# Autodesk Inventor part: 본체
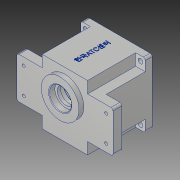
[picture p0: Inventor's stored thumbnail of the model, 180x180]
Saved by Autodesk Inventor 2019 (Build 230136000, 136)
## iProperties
Created: 2020-01
Part Number: 본체
Material: 알루미늄 6061
Document SubType Name: Modeling
Designer: 323-8
Density: 2.7 g/cm^3
Appearance: 알루미늄 - 평지
Mass: 876.342 g
Surface Area: 793.819 cm^2
Volume: 324.571 cm^3
Author: 323-8
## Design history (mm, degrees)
sketch "스케치1"
  geometry: L1 (-47, 47)-(47, 47); L2 (47, 47)-(47, -47); L3 (47, -47)-(-47, -47); L4 (-47, -47)-(-47, 47); L5 (-47, 47)-(47, -47); L6 (47, 47)-(-47, -47); L7 (-70, 30)-(70, 30); L8 (70, 30)-(70, -30); L9 (70, -30)-(-70, -30); L10 (-70, -30)-(-70, 30); L11 (-70, 30)-(70, -30); L12 (70, 30)-(-70, -30); 1 further point
  constraints: 24 end point, 4 midpoint, 4 parallel, 2 horizontal, 2 perpendicular
  dimensions: "d0" = 94 distance of L2.end L3.end; "d1" = 94 distance of L1.end L2.end; "d2" = 140 distance of L8.end L9.end; "d3" = 60 distance of L7.end L8.end
extrude "돌출1" new body sketch "스케치1" distance "d4" = 80; taper "d5" = 0 deg
sketch "스케치2"
  geometry: L1 (-33, 30)-(33, 30); L2 (33, 30)-(33, -30); L3 (33, -30)-(-33, -30); L4 (-33, -30)-(-33, 30); L5 (-33, 30)-(33, -30); L6 (33, 30)-(-33, -30); L7 (47, 47)-(47, 30) reference; L8 (33, 30)-(47, 30); L9 (47, 30)-(47, 47); L10 (47, 47)-(33, 47); L11 (33, 47)-(33, 30); 1 further point
  constraints: 20 end point, 4 parallel, 2 horizontal, 2 midpoint, 2 perpendicular
  dimensions: "d6" = 66 distance of L2.end L3.end; "d7" = 60 distance of L1.end L2.end
extrude "돌출2" cut sketch "스케치2" distance "d8" = 70; taper "d9" = 0 deg
sketch "스케치3"
  geometry: C1 r 27.5 at (0, 11); 1 further point
  constraints: 1 centre point, 1 vertical alignment
  dimensions: "d10" = 55 diameter of C1; "d11" = 11 distance of C1.centre point (0, 0)
extrude "돌출3" join sketch "스케치3" distance "d12" = 7; taper "d13" = 0 deg
sketch "스케치4"
  geometry: C1 r 40 at (0, 0); 1 further point
  constraints: 1 centre point, 1 coincident
  dimensions: "d14" = 80 diameter of C1
extrude "돌출4" cut sketch "스케치4" distance "d15" = 71; taper "d16" = 0 deg
sketch "스케치5"
  geometry: C1 r 43 at (0, 0); 1 further point
  constraints: 1 centre point, 1 coincident
  dimensions: "d17" = 86 diameter of C1
extrude "돌출5" cut sketch "스케치5" distance "d18" = 9; taper "d19" = 0 deg
sketch "스케치6"
  geometry: C1 r 21 at (0, 11); C2 r 15 at (0, -20); 1 further point
  constraints: 2 centre point, 2 vertical alignment
  dimensions: "d24" = 21 radius of C1; "d25" = 15 radius of C2; "d26" = 11 distance of point (0, 0) C1.centre; "d27" = 20 distance of point (0, 0) C2.centre
extrude "돌출6" join sketch "스케치6" distance "d28" = 7; taper "d29" = 0 deg
sketch "스케치7"
  geometry: C1 r 17.5 at (0, 11); A1 r 21 centre (0, 11) between (8.978, -7.984) and (-8.978, -7.984) reference; 1 further point
  constraints: 1 centre point, 1 coincident
  dimensions: "d30" = 35 diameter of C1
extrude "돌출7" cut sketch "스케치7" distance "d31" = 10; taper "d32" = 0 deg
sketch "스케치8"
  geometry: C1 r 11 at (0, -20); A1 r 15 centre (0, -20) between (-8.978, -7.984) and (8.978, -7.984) reference; 1 further point
  constraints: 1 centre point, 1 coincident
  dimensions: "d33" = 22 diameter of C1
extrude "돌출8" cut sketch "스케치8" distance "d34" = 7; taper "d35" = 0 deg
sketch "스케치9"
  geometry: 1 further point
sketch "스케치10"
  geometry: C1 r 11 at (0, 0) reference; C2 r 9.5 at (0, 0); 1 further point
  constraints: 1 centre point, 1 coincident
  dimensions: "d36" = 19 diameter of C2
extrude "돌출9" cut sketch "스케치10" distance "d37" = 3; taper "d38" = 0 deg
sketch "스케치11"
  geometry: C1 r 16 at (0, 0); C2 r 27.5 at (0, 0) reference; 1 further point
  constraints: 1 centre point, 1 concentric
  dimensions: "d39" = 32 diameter of C1
extrude "돌출10" cut sketch "스케치11" distance "d40" = 8.3; taper "d41" = 0 deg
sketch "스케치12"
  geometry: C1 r 12.5 at (0, 0); C2 r 16 at (0, 0) reference; 1 further point
  constraints: 1 centre point, 1 concentric
  dimensions: "d42" = 25 diameter of C1
extrude "돌출11" cut sketch "스케치12" stored distance "d43" = 8.3; taper "d44" = 0 deg
sketch "스케치13"
  geometry: L1 (-40, 40)-(40, 40); L2 (40, 40)-(40, -40); L3 (40, -40)-(-40, -40); L4 (-40, -40)-(-40, 40); L5 (-40, 40)-(40, -40); L6 (40, 40)-(-40, -40); C1 r 3.5 at (40, 40); 1 further point
  constraints: 12 end point, 2 midpoint, 2 parallel, 1 centre point, 1 coincident, 1 horizontal, 1 perpendicular
  dimensions: "d45" = 80 distance of L2.end L3.end; "d46" = 80 distance of L1.end L2.end; "d47" = 7 diameter of C1
extrude "돌출12" cut sketch "스케치13" extent not by distance; stored distance "d48" = 8.3; taper "d49" = 0 deg
sketch "스케치14"
  geometry: L1 (-60, 19)-(60, 19); L2 (60, 19)-(60, -19); L3 (60, -19)-(-60, -19); L4 (-60, -19)-(-60, 19); L5 (-60, 19)-(60, -19); L6 (60, 19)-(-60, -19); C1 r 2.25 at (60, 19); 1 further point
  constraints: 12 end point, 2 midpoint, 2 parallel, 1 centre point, 1 coincident, 1 horizontal, 1 perpendicular
  dimensions: "d50" = 120 distance of L2.end L3.end; "d51" = 38 distance of L1.end L2.end; "d52" = 4.5 diameter of C1
sketch "스케치15"
  geometry: L1 (-47, 47)-(47, -47); L2 (47, 47)-(-47, -47); L3 (70, 30)-(47, 30) reference; L4 (47, -47)-(47, -30) reference; L5 (70, 30)-(47, 30); L6 (47, 30)-(47, -30); L7 (47, -30)-(70, -30); L8 (70, -30)-(70, 30); 1 further point
  constraints: 12 end point, 2 midpoint, 2 parallel, 1 horizontal, 1 perpendicular
extrude "돌출13" cut sketch "스케치15" distance "d53" = 67; taper "d54" = 0 deg
extrude "돌출14" cut sketch "스케치14" extent not by distance; stored distance "d55" = 67; taper "d56" = 0 deg
sketch "스케치16"
  geometry: C1 r 2.25 at (10, -11) reference; C2 r 5 at (10, -11); 1 further point
  constraints: 1 centre point, 1 coincident
  dimensions: "d57" = 10 diameter of C2
extrude "돌출15" cut sketch "스케치16" distance "d58" = 5; taper "d59" = 0 deg
sketch "스케치17" dims "d60" = 36
  geometry: L1 (36, -4)-(39.799, -4); L2 (36, 4)-(39.799, 4); A1 r 4 centre (36, 0) between (36, 4) and (36, -4); A2 r 40 centre (0, 0) between (39.799, 4) and (39.799, -4) reference; A3 r 40 centre (0, 0) between (39.799, -4) and (39.799, 4); 2 further points
  constraints: 6 point on circle, 4 end point, 2 centre point, 2 coincident, 2 horizontal, 2 horizontal alignment, 2 tangent, 2 other
  dimensions: "d61" = 4 radius of A1
extrude "돌출16" join sketch "스케치17" stored distance "d62" = 0; taper "d63" = 0 deg
sketch "스케치18"
  geometry: A1 r 4 centre (36, 0) between (36, 4) and (36, -4) reference; 2 further points
  constraints: 1 coincident
hole "구멍1" sketch "스케치18" at (36, 0) diameter "d64" = 3.242; stored, may be unused: countersink angle "d68" = 90 deg, drill point angle "d70" = 118 deg; dims "d65" = 7, "d66" = 4, "d67" = 2, "d69" = 9
fillet "모깎기2" dims "d72" = 3
chamfer "모따기2" distance "d76" = 1; stored, may be unused: second distance "d77" = 2, angle "d78" = 45 deg
chamfer "모따기3" distance "d79" = 1; stored, may be unused: second distance "d80" = 2, angle "d81" = 30 deg
fillet "모깎기3" dims "d82" = 3
fillet "모깎기4" dims "d83" = 3
chamfer "모따기4" distance "d84" = 1; stored, may be unused: second distance "d85" = 2, angle "d86" = 30 deg
sketch "스케치19"
  geometry: L1 (-77, 80)-(11, 80) reference; L2 (-66, 0)-(0, 0) reference; 3 further points
  constraints: 1 midpoint, 1 vertical alignment, 1 other
  dimensions: "d87" = 40 distance from line of L1 point (-33, 40)
feature "엠보싱1" sketch "스케치19" dims "d88" = 0.5, "d89" = 0
node "솔리드1"
mirror "미러1"
mirror "미러2"
mirror "미러3"
mirror "미러4"
mirror "미러5"
mirror "미러6"
mirror "미러7"
mirror "미러8"
